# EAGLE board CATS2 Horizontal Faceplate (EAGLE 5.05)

Size 483 x 132.35 mm. Coordinates in mm from the lower left corner, seen from the top.
Outline: 0,0 483,0 483,132.35 0,132.35 0,0
Copper layers (1*16): Top 0.035mm / dielectric 1.5mm / Bottom 0.035mm
Design rules "default": minimum track width 10mil, minimum drill 0.6mm, track to track 8mil, track to pad 8mil, pad to pad 8mil, via to via 8mil, smd to smd 8mil, copper to edge 40mil, drill to drill 8mil, minimum pad ring 10mil, minimum via ring 8mil, stop-mask expansion 4mil, vias tented up to drill 0mil, thermal gap 10mil
Net classes: 1 Power: width 0.381 mm, drill 0.711 mm
Holes 12.7 mm at 64,20 84,20 84,40 130,40 130,20 157,40 157,20 184,40 184,20 211,40 211,20 238,40 238,20 265,40 265,20 292,40 292,20 319,40 319,20 346,40 346,20 418,40 393,20 393,40 418,20 338,-32 373,40
Holes 2.92 mm at 130,59 157,59 184,59 211,59 238,59 265,59 292,59 319,59 346,59 418,59 393,59 338,-22
Holes 6.35 mm at 9,5.85 9,21.73 9,37.6 9,50.3 9,66.17 9,82.05 9,94.75 9,110.62 9,126.5 474,5.85 474,21.73 474,37.6 474,50.3 474,66.17 474,82.05 474,94.75 474,110.62 474,126.5 338,-16

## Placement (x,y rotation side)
U$279  [TITLEBLOCK_PCB]  not placed on the board

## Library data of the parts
U$279 = QuantumOptics

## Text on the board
Measures: 132.35 | 132.35 (ref) | 126.5 | 110.625 | 94.75 | 82.05 | 66.175 | 59 | 50.3 | 40 | 37.6 | 20 | 21.725 | 5.85 | 0 | 0 (ref) | 0 | 9 | 64 | 84 | 130 | 157 | 184 | 211 | 238 | 265 | 292 | 319 | 346 | 373 | 393 | 418 | 474 | 483
Target: NOTES: | 0.25" | CATS2 - Faceplate, Back View | Material: 0.125" 6061 aluminum | Fits 19" Rack, 3U | J.Thywissen Labs | Outer dimensions +0.2mm -0.5mm | 0.115" +0.003 -0.002 | A. Stummer Nov 2009 | All dimensions are absolute, non-cumulative errors. | A | 0.505" -0.000 +0.010 | Can accept 0.5" and file.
